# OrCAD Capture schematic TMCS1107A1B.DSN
size A; title: TMCS1107 3% Basic Isolation Hall-Effect Current Sensor; rev: A
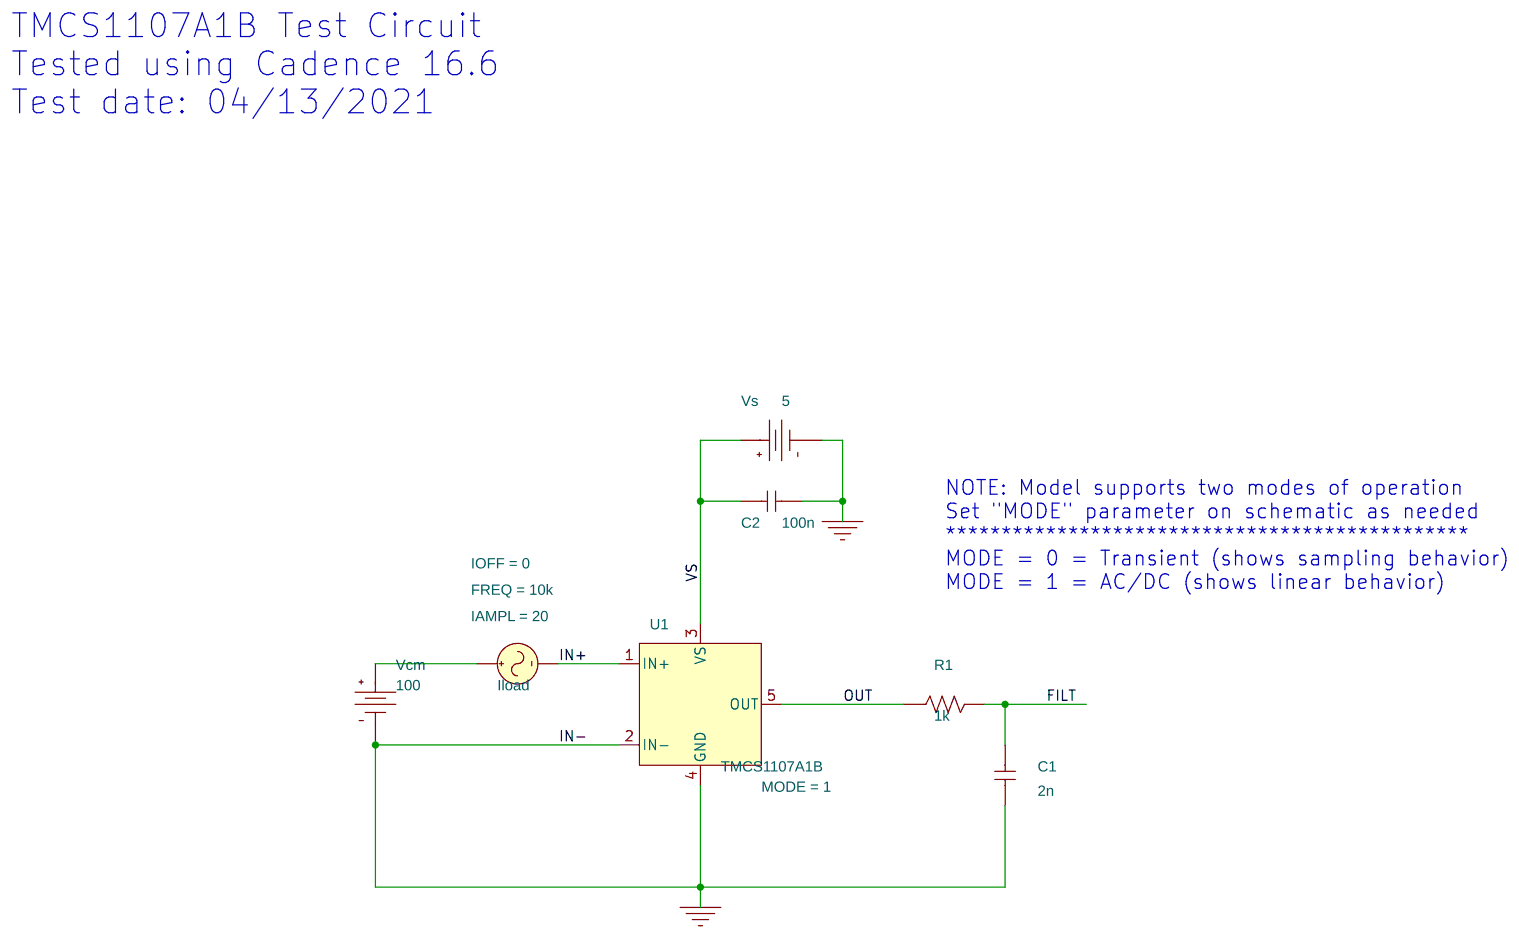
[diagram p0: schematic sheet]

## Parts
C1  2n  [RAD/CK05]
C2  100n  [RAD/CK05]
Iload  ISIN
R1  1k  [AX/RC05]
U1  TMCS1107A1B
Vcm  VDC
Vs  VDC

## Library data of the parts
C1 C2 = C
Iload = ISIN: FREQ: 10k; IAMPL: 20; IOFF: 0
R1 = R
U1 = TMCS1107A1B: MODE: 1
Vcm = VDC: DC: 100
Vs = VDC: DC: 5

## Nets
0: C1.1 C2.1 U1.2(IN-) U1.4(GND) Vcm.1(-) Vs.1(-)
FILT: C1.2 R1.2
IN+: Iload.2(-) U1.1(IN+)
OUT: R1.1 U1.5(OUT)
VS: C2.2 U1.3(VS) Vs.0(+)
N1374927: Iload.1(+) Vcm.0(+)

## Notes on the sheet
- TMCS1107A1B Test Circuit
  Tested using Cadence 16.6
  Test date: 04/13/2021
- NOTE: Model supports two modes of operation
  Set "MODE" parameter on schematic as needed
  ***********************************************
  MODE = 0 = Transient (shows sampling behavior)
  MODE = 1 = AC/DC (shows linear behavior)
